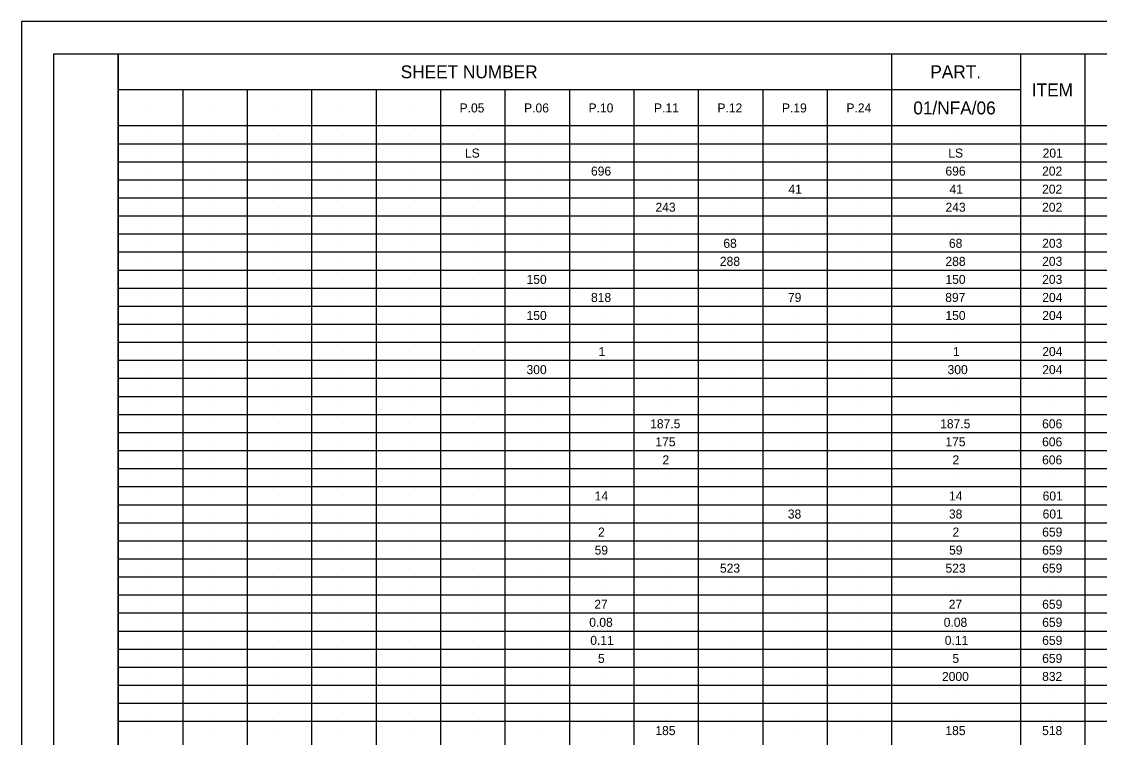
# Model space of a CAD drawing. Extents: x 0 to 34, y 0 to 22.
# Drawn here: x 0 to 16.73, y 10.89 to 22 of the extents above; entities that cross this region are included whole.
import ezdxf

# ---------------------------------------------------------------- set-up
doc = ezdxf.new("R2010")
doc.units = 0
for name, color, linetype in [('RD_P_RR_2', 7, 'Continuous'), ('RD_P_Text', 7, 'Continuous'), ('SC_Scratch1', 7, 'Continuous'), ('SH_Border', 7, 'Continuous'), ('SH_Cut_Line', 7, 'Continuous'), ('SH_Data', 7, 'Continuous')]:
    doc.layers.add(name, color=color, linetype=linetype)

msp = doc.modelspace()

# ---------------------------------------------------------------- linework, layer by layer
at = {"layer": 'SC_Scratch1'}
for p, q in [((2, 20.66), (2, 20.66)), ((3, 20.66), (3, 20.66)), ((4, 20.66), (4, 20.66)), ((5, 20.66), (5, 20.66)), ((6, 20.66), (6, 20.66)), ((7, 20.66), (7, 20.66)), ((8, 20.66), (8, 20.66)), ((9, 20.66), (9, 20.66)), ((10, 20.66), (10, 20.66)), ((11, 20.66), (11, 20.66)), ((12, 20.66), (12, 20.66)), ((13, 20.66), (13, 20.66)), ((14.5, 20.66), (14.5, 20.66)), ((2, 20.24), (2, 20.24)), ((3, 20.24), (3, 20.24)), ((4, 20.24), (4, 20.24)), ((5, 20.24), (5, 20.24)), ((6, 20.24), (6, 20.24)), ((7, 20.24), (7, 20.24)), ((8, 20.24), (8, 20.24)), ((9, 20.24), (9, 20.24)), ((10, 20.24), (10, 20.24)), ((11, 20.24), (11, 20.24)), ((12, 20.24), (12, 20.24)), ((13, 20.24), (13, 20.24)), ((14.5, 20.24), (14.5, 20.24)), ((16, 20.24), (16, 20.24)), ((2, 19.96), (2, 19.96)), ((3, 19.96), (3, 19.96)), ((4, 19.96), (4, 19.96)), ((5, 19.96), (5, 19.96)), ((6, 19.96), (6, 19.96)), ((7, 19.96), (7, 19.96)), ((8, 19.96), (8, 19.96)), ((9, 19.96), (9, 19.96)), ((10, 19.96), (10, 19.96)), ((11, 19.96), (11, 19.96)), ((12, 19.96), (12, 19.96)), ((13, 19.96), (13, 19.96)), ((14.5, 19.96), (14.5, 19.96)), ((16, 19.96), (16, 19.96)), ((2, 19.68), (2, 19.68)), ((3, 19.68), (3, 19.68)), ((4, 19.68), (4, 19.68)), ((5, 19.68), (5, 19.68)), ((6, 19.68), (6, 19.68)), ((7, 19.68), (7, 19.68)), ((8, 19.68), (8, 19.68)), ((9, 19.68), (9, 19.68)), ((10, 19.68), (10, 19.68)), ((11, 19.68), (11, 19.68)), ((12, 19.68), (12, 19.68)), ((13, 19.68), (13, 19.68)), ((14.5, 19.68), (14.5, 19.68)), ((16, 19.68), (16, 19.68)), ((2, 19.4), (2, 19.4)), ((3, 19.4), (3, 19.4)), ((4, 19.4), (4, 19.4)), ((5, 19.4), (5, 19.4)), ((6, 19.4), (6, 19.4)), ((7, 19.4), (7, 19.4)), ((8, 19.4), (8, 19.4)), ((9, 19.4), (9, 19.4)), ((10, 19.4), (10, 19.4)), ((11, 19.4), (11, 19.4)), ((12, 19.4), (12, 19.4)), ((13, 19.4), (13, 19.4)), ((14.5, 19.4), (14.5, 19.4)), ((16, 19.4), (16, 19.4)), ((2, 19.12), (2, 19.12)), ((3, 19.12), (3, 19.12)), ((4, 19.12), (4, 19.12)), ((5, 19.12), (5, 19.12)), ((6, 19.12), (6, 19.12)), ((7, 19.12), (7, 19.12)), ((8, 19.12), (8, 19.12)), ((9, 19.12), (9, 19.12)), ((10, 19.12), (10, 19.12)), ((11, 19.12), (11, 19.12)), ((12, 19.12), (12, 19.12)), ((13, 19.12), (13, 19.12)), ((14.5, 19.12), (14.5, 19.12)), ((16, 19.12), (16, 19.12)), ((2, 18.84), (2, 18.84)), ((3, 18.84), (3, 18.84)), ((4, 18.84), (4, 18.84)), ((5, 18.84), (5, 18.84)), ((6, 18.84), (6, 18.84)), ((7, 18.84), (7, 18.84)), ((8, 18.84), (8, 18.84)), ((9, 18.84), (9, 18.84)), ((10, 18.84), (10, 18.84)), ((11, 18.84), (11, 18.84)), ((12, 18.84), (12, 18.84)), ((13, 18.84), (13, 18.84)), ((14.5, 18.84), (14.5, 18.84)), ((16, 18.84), (16, 18.84)), ((2, 18.56), (2, 18.56)), ((3, 18.56), (3, 18.56)), ((4, 18.56), (4, 18.56)), ((5, 18.56), (5, 18.56)), ((6, 18.56), (6, 18.56)), ((7, 18.56), (7, 18.56)), ((8, 18.56), (8, 18.56)), ((9, 18.56), (9, 18.56)), ((10, 18.56), (10, 18.56)), ((11, 18.56), (11, 18.56)), ((12, 18.56), (12, 18.56)), ((13, 18.56), (13, 18.56)), ((14.5, 18.56), (14.5, 18.56)), ((16, 18.56), (16, 18.56)), ((2, 18.28), (2, 18.28)), ((3, 18.28), (3, 18.28)), ((4, 18.28), (4, 18.28)), ((5, 18.28), (5, 18.28)), ((6, 18.28), (6, 18.28)), ((7, 18.28), (7, 18.28)), ((8, 18.28), (8, 18.28)), ((9, 18.28), (9, 18.28)), ((10, 18.28), (10, 18.28)), ((11, 18.28), (11, 18.28)), ((12, 18.28), (12, 18.28)), ((13, 18.28), (13, 18.28)), ((14.5, 18.28), (14.5, 18.28)), ((16, 18.28), (16, 18.28)), ((2, 18), (2, 18)), ((3, 18), (3, 18)), ((4, 18), (4, 18)), ((5, 18), (5, 18)), ((6, 18), (6, 18)), ((7, 18), (7, 18)), ((8, 18), (8, 18)), ((9, 18), (9, 18)), ((10, 18), (10, 18)), ((11, 18), (11, 18)), ((12, 18), (12, 18)), ((13, 18), (13, 18)), ((14.5, 18), (14.5, 18)), ((16, 18), (16, 18)), ((2, 17.72), (2, 17.72)), ((3, 17.72), (3, 17.72)), ((4, 17.72), (4, 17.72)), ((5, 17.72), (5, 17.72)), ((6, 17.72), (6, 17.72)), ((7, 17.72), (7, 17.72)), ((8, 17.72), (8, 17.72)), ((9, 17.72), (9, 17.72)), ((10, 17.72), (10, 17.72)), ((11, 17.72), (11, 17.72)), ((12, 17.72), (12, 17.72)), ((13, 17.72), (13, 17.72)), ((14.5, 17.72), (14.5, 17.72)), ((16, 17.72), (16, 17.72)), ((2, 17.44), (2, 17.44)), ((3, 17.44), (3, 17.44)), ((4, 17.44), (4, 17.44)), ((5, 17.44), (5, 17.44)), ((6, 17.44), (6, 17.44)), ((7, 17.44), (7, 17.44)), ((8, 17.44), (8, 17.44)), ((9, 17.44), (9, 17.44)), ((10, 17.44), (10, 17.44)), ((11, 17.44), (11, 17.44)), ((12, 17.44), (12, 17.44)), ((13, 17.44), (13, 17.44)), ((14.5, 17.44), (14.5, 17.44)), ((16, 17.44), (16, 17.44)), ((2, 17.16), (2, 17.16)), ((3, 17.16), (3, 17.16)), ((4, 17.16), (4, 17.16)), ((5, 17.16), (5, 17.16)), ((6, 17.16), (6, 17.16)), ((7, 17.16), (7, 17.16)), ((8, 17.16), (8, 17.16)), ((9, 17.16), (9, 17.16)), ((10, 17.16), (10, 17.16)), ((11, 17.16), (11, 17.16)), ((12, 17.16), (12, 17.16)), ((13, 17.16), (13, 17.16)), ((14.5, 17.16), (14.5, 17.16)), ((16, 17.16), (16, 17.16)), ((2, 16.88), (2, 16.88)), ((3, 16.88), (3, 16.88)), ((4, 16.88), (4, 16.88)), ((5, 16.88), (5, 16.88)), ((6, 16.88), (6, 16.88)), ((7, 16.88), (7, 16.88)), ((8, 16.88), (8, 16.88)), ((9, 16.88), (9, 16.88)), ((10, 16.88), (10, 16.88)), ((11, 16.88), (11, 16.88)), ((12, 16.88), (12, 16.88)), ((13, 16.88), (13, 16.88)), ((14.5, 16.88), (14.5, 16.88)), ((16, 16.88), (16, 16.88)), ((2, 16.6), (2, 16.6)), ((3, 16.6), (3, 16.6)), ((4, 16.6), (4, 16.6)), ((5, 16.6), (5, 16.6)), ((6, 16.6), (6, 16.6)), ((7, 16.6), (7, 16.6)), ((8, 16.6), (8, 16.6)), ((9, 16.6), (9, 16.6)), ((10, 16.6), (10, 16.6)), ((11, 16.6), (11, 16.6)), ((12, 16.6), (12, 16.6)), ((13, 16.6), (13, 16.6)), ((14.5, 16.6), (14.5, 16.6)), ((16, 16.6), (16, 16.6)), ((2, 16.32), (2, 16.32)), ((3, 16.32), (3, 16.32)), ((4, 16.32), (4, 16.32)), ((5, 16.32), (5, 16.32)), ((6, 16.32), (6, 16.32)), ((7, 16.32), (7, 16.32)), ((8, 16.32), (8, 16.32)), ((9, 16.32), (9, 16.32)), ((10, 16.32), (10, 16.32)), ((11, 16.32), (11, 16.32)), ((12, 16.32), (12, 16.32)), ((13, 16.32), (13, 16.32)), ((14.5, 16.32), (14.5, 16.32)), ((16, 16.32), (16, 16.32)), ((2, 16.04), (2, 16.04)), ((3, 16.04), (3, 16.04)), ((4, 16.04), (4, 16.04)), ((5, 16.04), (5, 16.04)), ((6, 16.04), (6, 16.04)), ((7, 16.04), (7, 16.04)), ((8, 16.04), (8, 16.04)), ((9, 16.04), (9, 16.04)), ((10, 16.04), (10, 16.04)), ((11, 16.04), (11, 16.04)), ((12, 16.04), (12, 16.04)), ((13, 16.04), (13, 16.04)), ((14.5, 16.04), (14.5, 16.04)), ((16, 16.04), (16, 16.04)), ((2, 15.76), (2, 15.76)), ((3, 15.76), (3, 15.76)), ((4, 15.76), (4, 15.76)), ((5, 15.76), (5, 15.76)), ((6, 15.76), (6, 15.76)), ((7, 15.76), (7, 15.76)), ((8, 15.76), (8, 15.76)), ((9, 15.76), (9, 15.76)), ((10, 15.76), (10, 15.76)), ((11, 15.76), (11, 15.76)), ((12, 15.76), (12, 15.76)), ((13, 15.76), (13, 15.76)), ((14.5, 15.76), (14.5, 15.76)), ((16, 15.76), (16, 15.76)), ((2, 15.48), (2, 15.48)), ((3, 15.48), (3, 15.48)), ((4, 15.48), (4, 15.48)), ((5, 15.48), (5, 15.48)), ((6, 15.48), (6, 15.48)), ((7, 15.48), (7, 15.48)), ((8, 15.48), (8, 15.48)), ((9, 15.48), (9, 15.48)), ((10, 15.48), (10, 15.48)), ((11, 15.48), (11, 15.48)), ((12, 15.48), (12, 15.48)), ((13, 15.48), (13, 15.48)), ((14.5, 15.48), (14.5, 15.48)), ((16, 15.48), (16, 15.48)), ((2, 15.2), (2, 15.2)), ((3, 15.2), (3, 15.2)), ((4, 15.2), (4, 15.2)), ((5, 15.2), (5, 15.2)), ((6, 15.2), (6, 15.2)), ((7, 15.2), (7, 15.2)), ((8, 15.2), (8, 15.2)), ((9, 15.2), (9, 15.2)), ((10, 15.2), (10, 15.2)), ((11, 15.2), (11, 15.2)), ((12, 15.2), (12, 15.2)), ((13, 15.2), (13, 15.2)), ((14.5, 15.2), (14.5, 15.2)), ((16, 15.2), (16, 15.2)), ((2, 14.92), (2, 14.92)), ((3, 14.92), (3, 14.92)), ((4, 14.92), (4, 14.92)), ((5, 14.92), (5, 14.92)), ((6, 14.92), (6, 14.92)), ((7, 14.92), (7, 14.92)), ((8, 14.92), (8, 14.92)), ((9, 14.92), (9, 14.92)), ((10, 14.92), (10, 14.92)), ((11, 14.92), (11, 14.92)), ((12, 14.92), (12, 14.92)), ((13, 14.92), (13, 14.92)), ((14.5, 14.92), (14.5, 14.92)), ((16, 14.92), (16, 14.92)), ((2, 14.64), (2, 14.64)), ((3, 14.64), (3, 14.64)), ((4, 14.64), (4, 14.64)), ((5, 14.64), (5, 14.64)), ((6, 14.64), (6, 14.64)), ((7, 14.64), (7, 14.64)), ((8, 14.64), (8, 14.64)), ((9, 14.64), (9, 14.64)), ((10, 14.64), (10, 14.64)), ((11, 14.64), (11, 14.64)), ((12, 14.64), (12, 14.64)), ((13, 14.64), (13, 14.64)), ((14.5, 14.64), (14.5, 14.64)), ((16, 14.64), (16, 14.64)), ((2, 14.36), (2, 14.36)), ((3, 14.36), (3, 14.36)), ((4, 14.36), (4, 14.36)), ((5, 14.36), (5, 14.36)), ((6, 14.36), (6, 14.36)), ((7, 14.36), (7, 14.36)), ((8, 14.36), (8, 14.36)), ((9, 14.36), (9, 14.36)), ((10, 14.36), (10, 14.36)), ((11, 14.36), (11, 14.36)), ((12, 14.36), (12, 14.36)), ((13, 14.36), (13, 14.36)), ((14.5, 14.36), (14.5, 14.36)), ((16, 14.36), (16, 14.36)), ((2, 14.08), (2, 14.08)), ((3, 14.08), (3, 14.08)), ((4, 14.08), (4, 14.08)), ((5, 14.08), (5, 14.08)), ((6, 14.08), (6, 14.08)), ((7, 14.08), (7, 14.08)), ((8, 14.08), (8, 14.08)), ((9, 14.08), (9, 14.08)), ((10, 14.08), (10, 14.08)), ((11, 14.08), (11, 14.08)), ((12, 14.08), (12, 14.08)), ((13, 14.08), (13, 14.08)), ((14.5, 14.08), (14.5, 14.08)), ((16, 14.08), (16, 14.08)), ((2, 13.8), (2, 13.8)), ((3, 13.8), (3, 13.8)), ((4, 13.8), (4, 13.8)), ((5, 13.8), (5, 13.8)), ((6, 13.8), (6, 13.8)), ((7, 13.8), (7, 13.8)), ((8, 13.8), (8, 13.8)), ((9, 13.8), (9, 13.8)), ((10, 13.8), (10, 13.8)), ((11, 13.8), (11, 13.8)), ((12, 13.8), (12, 13.8)), ((13, 13.8), (13, 13.8)), ((14.5, 13.8), (14.5, 13.8)), ((16, 13.8), (16, 13.8)), ((2, 13.52), (2, 13.52)), ((3, 13.52), (3, 13.52)), ((4, 13.52), (4, 13.52)), ((5, 13.52), (5, 13.52)), ((6, 13.52), (6, 13.52)), ((7, 13.52), (7, 13.52)), ((8, 13.52), (8, 13.52)), ((9, 13.52), (9, 13.52)), ((10, 13.52), (10, 13.52)), ((11, 13.52), (11, 13.52)), ((12, 13.52), (12, 13.52)), ((13, 13.52), (13, 13.52)), ((14.5, 13.52), (14.5, 13.52)), ((16, 13.52), (16, 13.52)), ((2, 13.24), (2, 13.24)), ((3, 13.24), (3, 13.24)), ((4, 13.24), (4, 13.24)), ((5, 13.24), (5, 13.24)), ((6, 13.24), (6, 13.24)), ((7, 13.24), (7, 13.24)), ((8, 13.24), (8, 13.24)), ((9, 13.24), (9, 13.24)), ((10, 13.24), (10, 13.24)), ((11, 13.24), (11, 13.24)), ((12, 13.24), (12, 13.24)), ((13, 13.24), (13, 13.24)), ((14.5, 13.24), (14.5, 13.24)), ((16, 13.24), (16, 13.24)), ((2, 12.96), (2, 12.96)), ((3, 12.96), (3, 12.96)), ((4, 12.96), (4, 12.96)), ((5, 12.96), (5, 12.96)), ((6, 12.96), (6, 12.96)), ((7, 12.96), (7, 12.96)), ((8, 12.96), (8, 12.96)), ((9, 12.96), (9, 12.96)), ((10, 12.96), (10, 12.96)), ((11, 12.96), (11, 12.96)), ((12, 12.96), (12, 12.96)), ((13, 12.96), (13, 12.96)), ((14.5, 12.96), (14.5, 12.96)), ((16, 12.96), (16, 12.96)), ((2, 12.68), (2, 12.68)), ((3, 12.68), (3, 12.68)), ((4, 12.68), (4, 12.68)), ((5, 12.68), (5, 12.68)), ((6, 12.68), (6, 12.68)), ((7, 12.68), (7, 12.68)), ((8, 12.68), (8, 12.68)), ((9, 12.68), (9, 12.68)), ((10, 12.68), (10, 12.68)), ((11, 12.68), (11, 12.68)), ((12, 12.68), (12, 12.68)), ((13, 12.68), (13, 12.68)), ((14.5, 12.68), (14.5, 12.68)), ((16, 12.68), (16, 12.68)), ((2, 12.4), (2, 12.4)), ((3, 12.4), (3, 12.4)), ((4, 12.4), (4, 12.4)), ((5, 12.4), (5, 12.4)), ((6, 12.4), (6, 12.4)), ((7, 12.4), (7, 12.4)), ((8, 12.4), (8, 12.4)), ((9, 12.4), (9, 12.4)), ((10, 12.4), (10, 12.4)), ((11, 12.4), (11, 12.4)), ((12, 12.4), (12, 12.4)), ((13, 12.4), (13, 12.4)), ((14.5, 12.4), (14.5, 12.4)), ((16, 12.4), (16, 12.4)), ((2, 12.12), (2, 12.12)), ((3, 12.12), (3, 12.12)), ((4, 12.12), (4, 12.12)), ((5, 12.12), (5, 12.12)), ((6, 12.12), (6, 12.12)), ((7, 12.12), (7, 12.12)), ((8, 12.12), (8, 12.12)), ((9, 12.12), (9, 12.12)), ((10, 12.12), (10, 12.12)), ((11, 12.12), (11, 12.12)), ((12, 12.12), (12, 12.12)), ((13, 12.12), (13, 12.12)), ((14.5, 12.12), (14.5, 12.12)), ((16, 12.12), (16, 12.12)), ((2, 11.84), (2, 11.84)), ((3, 11.84), (3, 11.84)), ((4, 11.84), (4, 11.84)), ((5, 11.84), (5, 11.84)), ((6, 11.84), (6, 11.84)), ((7, 11.84), (7, 11.84)), ((8, 11.84), (8, 11.84)), ((9, 11.84), (9, 11.84)), ((10, 11.84), (10, 11.84)), ((11, 11.84), (11, 11.84)), ((12, 11.84), (12, 11.84)), ((13, 11.84), (13, 11.84)), ((14.5, 11.84), (14.5, 11.84)), ((16, 11.84), (16, 11.84)), ((2, 11.56), (2, 11.56)), ((3, 11.56), (3, 11.56)), ((4, 11.56), (4, 11.56)), ((5, 11.56), (5, 11.56)), ((6, 11.56), (6, 11.56)), ((7, 11.56), (7, 11.56)), ((8, 11.56), (8, 11.56)), ((9, 11.56), (9, 11.56)), ((10, 11.56), (10, 11.56)), ((11, 11.56), (11, 11.56)), ((12, 11.56), (12, 11.56)), ((13, 11.56), (13, 11.56)), ((14.5, 11.56), (14.5, 11.56)), ((16, 11.56), (16, 11.56)), ((2, 11.28), (2, 11.28)), ((3, 11.28), (3, 11.28)), ((4, 11.28), (4, 11.28)), ((5, 11.28), (5, 11.28)), ((6, 11.28), (6, 11.28)), ((7, 11.28), (7, 11.28)), ((8, 11.28), (8, 11.28)), ((9, 11.28), (9, 11.28)), ((10, 11.28), (10, 11.28)), ((11, 11.28), (11, 11.28)), ((12, 11.28), (12, 11.28)), ((13, 11.28), (13, 11.28)), ((14.5, 11.28), (14.5, 11.28)), ((16, 11.28), (16, 11.28)), ((2, 11), (2, 11)), ((3, 11), (3, 11)), ((4, 11), (4, 11)), ((5, 11), (5, 11)), ((6, 11), (6, 11)), ((7, 11), (7, 11)), ((8, 11), (8, 11)), ((9, 11), (9, 11)), ((10, 11), (10, 11)), ((11, 11), (11, 11)), ((12, 11), (12, 11)), ((13, 11), (13, 11)), ((14.5, 11), (14.5, 11)), ((16, 11), (16, 11))]:
    msp.add_line(p, q, dxfattribs=at)
at = {"layer": 'SH_Border'}
for points in [[(0.5, 21.5), (1.5, 21.5), (1.5, 0.5), (0.5, 0.5)], [(1.5, 21.5), (33.5, 21.5), (33.5, 0.5), (1.5, 0.5)]]:
    msp.add_lwpolyline(points, close=True, dxfattribs=at)
at = {"layer": 'SH_Cut_Line'}
msp.add_lwpolyline([(0, 0), (34, 0), (34, 22), (0, 22)], close=True, dxfattribs=at)
at = {"layer": 'SH_Data'}
for p, q in [((13.5, 21.5), (13.5, 0.5)), ((15.5, 21.5), (15.5, 0.5)), ((16.5, 21.5), (16.5, 0.5)), ((15.5, 20.94), (1.5, 20.94)), ((2.5, 20.94), (2.5, 0.5)), ((3.5, 20.94), (3.5, 0.5)), ((4.5, 20.94), (4.5, 0.5)), ((5.5, 20.94), (5.5, 0.5)), ((6.5, 20.94), (6.5, 0.5)), ((7.5, 20.94), (7.5, 0.5)), ((8.5, 20.94), (8.5, 0.5)), ((9.5, 20.94), (9.5, 0.5)), ((10.5, 20.94), (10.5, 0.5)), ((11.5, 20.94), (11.5, 0.5)), ((12.5, 20.94), (12.5, 0.5)), ((13.5, 20.94), (13.5, 0.5)), ((32, 20.38), (1.5, 20.38)), ((32, 20.1), (1.5, 20.1)), ((32, 19.82), (1.5, 19.82)), ((32, 19.54), (1.5, 19.54)), ((32, 19.26), (1.5, 19.26)), ((32, 18.98), (1.5, 18.98)), ((32, 18.7), (1.5, 18.7)), ((32, 18.42), (1.5, 18.42)), ((32, 18.14), (1.5, 18.14)), ((32, 17.86), (1.5, 17.86)), ((32, 17.58), (1.5, 17.58)), ((32, 17.3), (1.5, 17.3)), ((32, 17.02), (1.5, 17.02)), ((32, 16.74), (1.5, 16.74)), ((32, 16.46), (1.5, 16.46)), ((32, 16.18), (1.5, 16.18)), ((32, 15.9), (1.5, 15.9)), ((32, 15.62), (1.5, 15.62)), ((32, 15.34), (1.5, 15.34)), ((32, 15.06), (1.5, 15.06)), ((32, 14.78), (1.5, 14.78)), ((32, 14.5), (1.5, 14.5)), ((32, 14.22), (1.5, 14.22)), ((32, 13.94), (1.5, 13.94)), ((32, 13.66), (1.5, 13.66)), ((32, 13.38), (1.5, 13.38)), ((32, 13.1), (1.5, 13.1)), ((32, 12.82), (1.5, 12.82)), ((32, 12.54), (1.5, 12.54)), ((32, 12.26), (1.5, 12.26)), ((32, 11.98), (1.5, 11.98)), ((32, 11.7), (1.5, 11.7)), ((32, 11.42), (1.5, 11.42)), ((32, 11.14), (1.5, 11.14))]:
    msp.add_line(p, q, dxfattribs=at)

# ---------------------------------------------------------------- texts
at = {"layer": 'RD_P_RR_2'}
for s, p in [('LS', (6.88, 19.89)), ('288', (10.836, 18.21))]:
    msp.add_text(s, height=0.14, dxfattribs=at).set_placement(p)
at = {"layer": 'RD_P_Text'}
for s, p in [('P.05', (6.797, 20.59)), ('P.06', (7.798, 20.59)), ('P.10', (8.798, 20.59)), ('P.11', (9.814, 20.59)), ('P.12', (10.798, 20.59)), ('P.19', (11.799, 20.59)), ('P.24', (12.8, 20.59)), ('LS', (14.38, 19.89)), ('201', (15.844, 19.89)), ('696', (8.836, 19.61)), ('696', (14.336, 19.61)), ('202', (15.836, 19.61)), ('41', (11.899, 19.33)), ('41', (14.399, 19.33)), ('202', (15.836, 19.33)), ('243', (9.837, 19.05)), ('243', (14.337, 19.05)), ('202', (15.836, 19.05)), ('68', (10.89, 18.49)), ('68', (14.39, 18.49)), ('203', (15.837, 18.49)), ('288', (14.336, 18.21)), ('203', (15.837, 18.21)), ('150', (7.836, 17.93)), ('150', (14.336, 17.93)), ('203', (15.837, 17.93)), ('818', (8.836, 17.65)), ('79', (11.892, 17.65)), ('897', (14.333, 17.65)), ('204', (15.838, 17.65)), ('150', (7.836, 17.37)), ('150', (14.336, 17.37)), ('204', (15.838, 17.37)), ('1', (8.953, 16.81)), ('1', (14.453, 16.81)), ('204', (15.838, 16.81)), ('300', (7.836, 16.53)), ('300', (14.369, 16.53)), ('204', (15.838, 16.53)), ('187.5', (9.754, 15.69)), ('187.5', (14.254, 15.69)), ('606', (15.836, 15.69)), ('175', (9.835, 15.41)), ('175', (14.335, 15.41)), ('606', (15.836, 15.41)), ('2', (9.945, 15.13)), ('2', (14.445, 15.13)), ('606', (15.836, 15.13)), ('14', (8.892, 14.57)), ('14', (14.392, 14.57)), ('601', (15.844, 14.57)), ('38', (11.89, 14.29)), ('38', (14.39, 14.29)), ('601', (15.844, 14.29)), ('2', (8.945, 14.01)), ('2', (14.445, 14.01)), ('659', (15.837, 14.01)), ('59', (8.892, 13.73)), ('59', (14.392, 13.73)), ('659', (15.837, 13.73)), ('523', (10.837, 13.45)), ('523', (14.337, 13.45)), ('659', (15.837, 13.45)), ('27', (8.887, 12.89)), ('27', (14.387, 12.89)), ('659', (15.837, 12.89)), ('0.08', (8.809, 12.61)), ('0.08', (14.309, 12.61)), ('659', (15.837, 12.61)), ('0.11', (8.825, 12.33)), ('0.11', (14.325, 12.33)), ('659', (15.837, 12.33)), ('5', (8.944, 12.05)), ('5', (14.444, 12.05)), ('659', (15.837, 12.05)), ('2000', (14.282, 11.77)), ('832', (15.836, 11.77)), ('185', (9.835, 10.93)), ('185', (14.335, 10.93)), ('518', (15.836, 10.93))]:
    msp.add_text(s, height=0.14, dxfattribs=at).set_placement(p)
at = {"layer": 'SH_Data'}
for s, p in [('SHEET NUMBER', (5.883, 21.12)), ('PART.', (14.101, 21.12)), ('ITEM', (15.676, 20.84)), ('01/NFA/06', (13.837, 20.56))]:
    msp.add_text(s, height=0.2, dxfattribs=at).set_placement(p)

doc.saveas('drawing.dxf')
